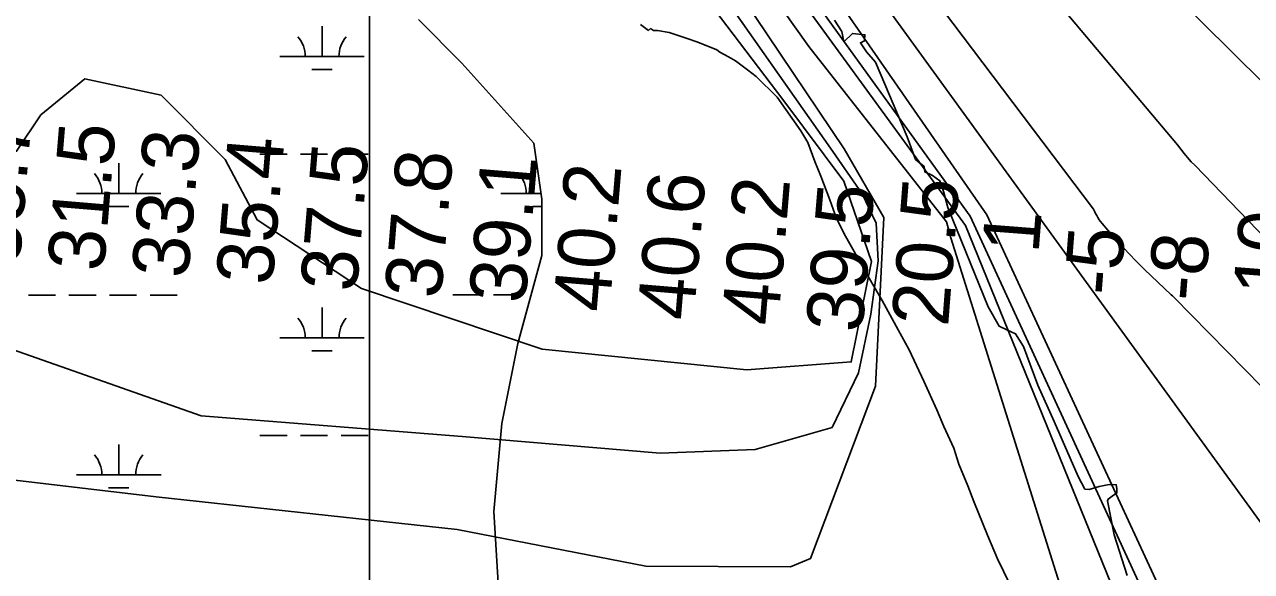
# Model space of a CAD drawing. Extents: x 3263578 to 3301413, y 764927 to 798602.
# Drawn here: x 3290909 to 3292360, y 777527 to 778174 of the extents above; entities that cross this region are included whole.
import ezdxf

# ---------------------------------------------------------------- set-up
doc = ezdxf.new("R2010")
doc.units = 0
for name, color, linetype in [('V-GRID-MAJR', 7, 'Continuous'), ('V-RIVR-EDGE', 7, 'Continuous'), ('V-RIVR-RANG', 7, 'Continuous'), ('V-SITE-VEGE', 7, 'Continuous'), ('V-TOPO-DPTH', 7, 'Continuous'), ('V-TOPO-MAJR', 7, 'Continuous'), ('V-TOPO-MINR', 7, 'Continuous'), ('V-TOPO-WATR', 7, 'Continuous'), ('V-WETL-SWMP', 7, 'Continuous')]:
    doc.layers.add(name, color=color, linetype=linetype)

msp = doc.modelspace()

# ---------------------------------------------------------------- linework, layer by layer
at = {"layer": 'V-GRID-MAJR'}
msp.add_spline([(3291317.4, 775831.2), (3291315.6, 781890.6), (3291313.9, 787952.6), (3291312.1, 794014.7), (3291312.1, 794017.2)], degree=3, dxfattribs=at)
at = {"layer": 'V-RIVR-EDGE'}
msp.add_lwpolyline([(3291866.6, 778179.2), (3291875.2, 778165.7), (3291877.8, 778153.5), (3291887.8, 778163.5), (3291902.6, 778162.1), (3291902.1, 778154.7), (3291897.4, 778152.6), (3291904.7, 778141.7), (3291915.1, 778129.5), (3291952.7, 778041.2), (3291962.6, 778014.6), (3291972.6, 778006.3), (3291973.5, 777999.8), (3291982.6, 777995.5), (3291991.3, 777989.3), (3291996, 777975.4), (3292000.8, 777957.6), (3292048.3, 777840.1), (3292061.3, 777817.5), (3292070.4, 777813.1), (3292080.8, 777808.3), (3292090.3, 777793.5), (3292107.2, 777747.4), (3292126.6, 777704.7), (3292154.7, 777639.5), (3292162.9, 777624.7), (3292167.7, 777624.2), (3292179.9, 777627.7), (3292191.6, 777630.2), (3292199.9, 777629.8), (3292200.8, 777625.4), (3292200.7, 777620.2), (3292195.1, 777616.3), (3292190.3, 777612.9), (3292189.4, 777610.7), (3292197.6, 777570.7), (3292212.7, 777522.4)], dxfattribs=at)
at = {"layer": 'V-SITE-VEGE'}
for p, q in [((3291637.4, 778174.1), (3291646.7, 778167.1)), ((3291646.7, 778167.1), (3291649.1, 778169.4)), ((3291649.1, 778169.4), (3291652.6, 778167.1)), ((3291652.6, 778167.1), (3291657.2, 778167.1)), ((3291657.2, 778167.1), (3291671.3, 778164.8)), ((3291671.3, 778164.8), (3291691.1, 778157.9)), ((3291691.1, 778157.9), (3291705.2, 778153.2)), ((3291705.2, 778153.2), (3291727.4, 778144)), ((3291727.4, 778144), (3291730.9, 778141.6)), ((3291730.9, 778141.6), (3291741.4, 778135.8)), ((3291741.4, 778135.8), (3291749.6, 778131.2)), ((3291749.6, 778131.2), (3291763.6, 778120.7)), ((3291763.6, 778120.7), (3291774.2, 778112.6)), ((3291774.2, 778112.6), (3291798.8, 778088.1)), ((3291798.8, 778088.1), (3291826.9, 778048.5)), ((3291826.9, 778048.5), (3291835.1, 778034.5)), ((3291835.1, 778034.5), (3291843.4, 778012.3)), ((3291843.4, 778012.3), (3291850.4, 777994.8)), ((3291850.4, 777994.8), (3291861, 777966.8)), ((3291861, 777966.8), (3291869.2, 777944.6)), ((3291869.2, 777944.6), (3291879.8, 777923.7)), ((3291879.8, 777923.7), (3291909.1, 777871.2)), ((3291909.1, 777871.2), (3291923.2, 777847.9)), ((3291923.2, 777847.9), (3291942, 777812.9)), ((3291942, 777812.9), (3291954.9, 777789.5)), ((3291954.9, 777789.5), (3291972.5, 777752.2)), ((3291972.5, 777752.2), (3291987.8, 777718.4)), ((3291987.8, 777718.4), (3291996, 777698.6)), ((3291996, 777698.6), (3292007.8, 777672.9)), ((3292007.8, 777672.9), (3292013.7, 777654.2)), ((3292013.7, 777654.2), (3292024.3, 777628.6)), ((3292024.3, 777628.6), (3292031.3, 777609.9)), ((3292031.3, 777609.9), (3292047.8, 777570.2)), ((3292047.8, 777570.2), (3292059.5, 777542.2)), ((3292059.5, 777542.2), (3292073.6, 777513.1))]:
    msp.add_line(p, q, dxfattribs=at)
at = {"layer": 'V-TOPO-DPTH'}
for points in [[(3291532.3, 779020.6), (3291542.1, 779009.1), (3291551.6, 778997.2), (3291557.5, 778989.4), (3291569.1, 778973.1), (3291580.1, 778956.4), (3291590.2, 778939.1), (3291599.6, 778921.4), (3291834.6, 778639.5), (3291854.5, 778618.1), (3291855.8, 778616.8), (3291857.2, 778615.6), (3291858.6, 778614.4), (3291860.2, 778613.4), (3292631.7, 777850.1)], [(3291532.3, 779020.6), (3291542.1, 779009.1), (3291551.6, 778997.2), (3291557.5, 778989.4), (3291569.1, 778973.1), (3291580.1, 778956.4), (3291590.2, 778939.1), (3291599.6, 778921.4), (3291834.6, 778639.5), (3291854.5, 778618.1), (3291855.8, 778616.8), (3291857.2, 778615.6), (3291858.6, 778614.4), (3291860.2, 778613.4), (3292631.7, 777850.1)], [(3292279.7, 777300.8), (3292021.7, 777936.6), (3291470, 778693.2)], [(3292915.6, 777191.8), (3292268.2, 777851.5), (3292266.5, 777853.1), (3292264.8, 777854.6), (3292233.5, 777884.5), (3292224, 777893.8), (3292214.7, 777903.3), (3292205.7, 777913.1), (3292196.8, 777923), (3292183.2, 777938.8), (3292181.4, 777941), (3292179.7, 777943.3), (3292178.2, 777945.7), (3292176.8, 777948.1), (3292175.5, 777950.6), (3292174.2, 777953.2), (3292173, 777955.7), (3291614, 778695.4)], [(3292915.6, 777191.8), (3292268.2, 777851.5), (3292266.5, 777853.1), (3292264.8, 777854.6), (3292233.5, 777884.5), (3292224, 777893.8), (3292214.7, 777903.3), (3292205.7, 777913.1), (3292196.8, 777923), (3292183.2, 777938.8), (3292181.4, 777941), (3292179.7, 777943.3), (3292178.2, 777945.7), (3292176.8, 777948.1), (3292175.5, 777950.6), (3292174.2, 777953.2), (3292173, 777955.7), (3291614, 778695.4)], [(3291548.1, 778667.7), (3292046.9, 777949.1), (3292382, 777225.4)], [(3291548.1, 778667.7), (3292046.9, 777949.1), (3292382, 777225.4)]]:
    msp.add_lwpolyline(points, dxfattribs=at)
at = {"layer": 'V-TOPO-MAJR'}
msp.add_lwpolyline([(3290539.3, 777870.7), (3290835.8, 777810.2), (3291117.7, 777711.5), (3291426.2, 777686.8), (3291660.5, 777667.1), (3291772.9, 777671.6), (3291863.9, 777697.6), (3291895.1, 777762.1), (3291909.7, 777831.5), (3291918.2, 777894.8), (3291915.9, 777939.1), (3291899.3, 777973.8), (3291864.7, 778024.1), (3291709.8, 778244.5), (3291488.2, 778571.5), (3291395.2, 778708.1), (3291333.2, 778772.8), (3291271.1, 778808.9), (3291211.4, 778828.1), (3291173.1, 778830.6), (3291051.2, 778850.1), (3290979.6, 778898.1), (3290910.5, 779036.2)], dxfattribs=at)
at = {"layer": 'V-TOPO-MINR'}
for points in [[(3290152.1, 779735.8), (3290476.2, 779589.1), (3290851.3, 779318.7), (3290878.2, 779287.7), (3291001.3, 778993.7), (3291046.6, 778945.7), (3291075, 778925.5), (3291198, 778901.1), (3291254, 778879.6), (3291295.4, 778862.1), (3291339.5, 778829.9), (3291380.8, 778795.1), (3291430.2, 778734.8), (3291562, 778533.9), (3291836.4, 778148.3), (3291999, 777940.6), (3292004.3, 777921.9), (3292217.9, 777242.3)], [(3291532.3, 779020.6), (3291542.1, 779009.1), (3291551.6, 778997.2), (3291557.5, 778989.4), (3291569.1, 778973.1), (3291580.1, 778956.4), (3291590.2, 778939.1), (3291599.6, 778921.4), (3291834.6, 778639.5), (3291854.5, 778618.1), (3291855.8, 778616.8), (3291857.2, 778615.6), (3291858.6, 778614.4), (3291860.2, 778613.4), (3292631.7, 777850.1)], [(3291471, 779010.8), (3291483.6, 778998.2), (3291495.7, 778985), (3291507.4, 778971.5), (3291519.4, 778957.3), (3291529.8, 778944.2), (3291539.9, 778930.9), (3291549.4, 778917.2), (3291558.5, 778903.2), (3291566.9, 778888.7), (3291574.9, 778874.1), (3291582.1, 778859), (3291588.8, 778843.7), (3292272.3, 778031.7), (3292276.2, 778026.6), (3292280.2, 778021.6), (3292284.3, 778016.7), (3292288.6, 778011.9), (3292293.1, 778007.3), (3292408.3, 777888)], [(3291071.5, 778866.2), (3291074.9, 778865.5), (3291081.5, 778864.6), (3291088.2, 778863.9), (3291137.3, 778859.6), (3291143.5, 778859), (3291149.7, 778858.4), (3291155.8, 778857.7), (3291162, 778856.9), (3291168.1, 778856.2), (3291174.3, 778855.5), (3291180.5, 778854.8), (3291186.6, 778854.2), (3291237.6, 778849.1), (3291243.7, 778848.2), (3291249.8, 778847), (3291255.8, 778845.2), (3291261.6, 778843.1), (3291267.3, 778840.5), (3291272.7, 778837.5), (3291353.5, 778795.6), (3291370.1, 778775.1), (3291424.7, 778701.4), (3291878.2, 778027.1)], [(3291062.8, 778841), (3291236.5, 778807.5), (3291271.6, 778792.9), (3291357, 778721.5), (3291418.5, 778640.6), (3291640.9, 778302.8), (3291806.6, 778083.9), (3291877.6, 777988.8), (3291910.6, 777893.7), (3291886.6, 777775), (3291763.1, 777765.8), (3291520.9, 777790.1), (3291307.3, 777861.9), (3291184, 777943), (3291146.2, 778014.3), (3291070.4, 778090.5), (3290980.2, 778109.7), (3290927.9, 778067.1), (3290899.3, 778024.4), (3290813.7, 778000.9), (3290718.7, 777986.9), (3290566.7, 778001.5)], [(3291470, 778693.2), (3292021.7, 777936.6), (3292279.7, 777300.8)], [(3291614, 778695.4), (3292173, 777955.7), (3292174.2, 777953.2), (3292175.5, 777950.6), (3292176.8, 777948.1), (3292178.2, 777945.7), (3292179.7, 777943.3), (3292181.4, 777941), (3292183.2, 777938.8), (3292196.8, 777923), (3292205.7, 777913.1), (3292214.7, 777903.3), (3292224, 777893.8), (3292233.5, 777884.5), (3292264.8, 777854.6), (3292266.5, 777853.1), (3292268.2, 777851.5), (3292915.6, 777191.8)], [(3291513.3, 778659.2), (3292027.1, 777947.3), (3292722.7, 776437)], [(3291595.7, 778653.1), (3292574, 777305.4)], [(3291878.2, 778027.1), (3291925, 777945.9), (3291915, 777746.4), (3291838.5, 777542.4), (3291814.7, 777532.9), (3291643.7, 777533.4), (3291420.6, 777576.7), (3291064.5, 777615.5), (3290529, 777678.6)]]:
    msp.add_lwpolyline(points, dxfattribs=at)
at = {"layer": 'V-TOPO-WATR'}
msp.add_lwpolyline([(3291548.1, 778667.7), (3292046.9, 777949.1), (3292382, 777225.4)], dxfattribs=at)
at = {"layer": 'V-WETL-SWMP'}
for p, q in [((3291374.7, 778179.9), (3291425.9, 778128.5)), ((3291260.6, 778136.2), (3291260.6, 778172.2)), ((3291210.6, 778136.2), (3291310.6, 778136.2)), ((3291248.6, 778120.8), (3291272.6, 778120.8)), ((3291425.9, 778128.5), (3291511.1, 778033.8)), ((3291511.1, 778033.8), (3291520.6, 777967.5)), ((3291187.2, 778020.8), (3291219.2, 778020.8)), ((3291235.2, 778020.8), (3291267.2, 778020.8)), ((3291283.2, 778020.8), (3291315.2, 778020.8)), ((3291020.1, 777974.3), (3291020.1, 778010.3)), ((3290970.1, 777974.3), (3291070.1, 777974.3)), ((3291472, 777974.3), (3291519.6, 777974.3)), ((3291008.1, 777958.9), (3291032.1, 777958.9)), ((3291510, 777958.9), (3291520.6, 777958.9)), ((3291520.6, 777967.5), (3291520.6, 777901.1)), ((3291520.6, 777901.1), (3291492.2, 777796.9)), ((3290913.3, 777854.2), (3290945.3, 777854.2)), ((3290961.3, 777854.2), (3290993.3, 777854.2)), ((3291009.3, 777854.2), (3291041.3, 777854.2)), ((3291057.3, 777854.2), (3291089.3, 777854.2)), ((3291415.2, 777854.3), (3291447.2, 777854.3)), ((3291463.2, 777854.3), (3291495.2, 777854.3)), ((3291260.6, 777803.5), (3291260.6, 777839.5)), ((3291210.6, 777803.5), (3291310.6, 777803.5)), ((3291492.2, 777796.9), (3291473.3, 777702.2)), ((3291248.6, 777788.1), (3291272.6, 777788.1)), ((3291473.3, 777702.2), (3291463.8, 777598)), ((3291187.2, 777688.1), (3291219.2, 777688.1)), ((3291235.2, 777688.1), (3291267.2, 777688.1)), ((3291283.2, 777688.1), (3291315.2, 777688.1)), ((3291020.2, 777641.6), (3291020.2, 777677.6)), ((3290970.2, 777641.6), (3291070.2, 777641.6)), ((3291008.2, 777626.2), (3291032.2, 777626.2)), ((3291463.8, 777598), (3291473.3, 777436.9))]:
    msp.add_line(p, q, dxfattribs=at)
for centre, start, end in [((3291205.4, 778136.7), 359.2323, 40.776), ((3291315.8, 778136.7), 139.2323, 180.776), ((3290964.9, 777974.8), 359.2323, 40.776), ((3291075.4, 777974.8), 139.2323, 180.776), ((3291466.8, 777974.8), 359.2323, 40.776), ((3291205.4, 777804), 359.2323, 40.776), ((3291315.9, 777804), 139.2323, 180.776), ((3290964.9, 777642.1), 359.2323, 40.776), ((3291075.4, 777642.1), 139.2323, 180.776)]:
    msp.add_arc(centre, 35.2, start, end, dxfattribs=at)

# ---------------------------------------------------------------- texts
at = {"layer": 'V-RIVR-RANG'}
for s, rotation, p in [('35.7', 85.2583, (3290902.8, 777889.1)), ('31.5', 85.2583, (3291002.4, 777881.1)), ('33.3', 85.2583, (3291102.1, 777873)), ('35.4', 85.2583, (3291201.8, 777865)), ('37.5', 85.2583, (3291301.5, 777857)), ('37.8', 85.2583, (3291401.2, 777849)), ('39.1', 85.2583, (3291501, 777843.3)), ('40.2', 85.2583, (3291600.5, 777832.9)), ('40.6', 85.2583, (3291700, 777823.1)), ('40.2', 85.2583, (3291799.9, 777816.9)), ('20.5', 85.555, (3292001, 777816)), ('39.5', 85.2583, (3291899.5, 777808.9)), ('1', 85.555, (3292108, 777902.4)), ('-10', 85.555, (3292402.7, 777822)), ('-5', 85.555, (3292204.5, 777852.5)), ('-8', 85.555, (3292304.2, 777845.6))]:
    msp.add_text(s, height=67, rotation=rotation, dxfattribs=at).set_placement(p)

doc.saveas('drawing.dxf')
